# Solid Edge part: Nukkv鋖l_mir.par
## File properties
Author: Türk
Template: Iso Part.par
Last saved by: Türk
Revision: 7
Application: Solid Edge
Username: Türk
Accuracy: 0,990
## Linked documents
ll.par
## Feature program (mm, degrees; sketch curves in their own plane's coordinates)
part copy "CopiedPart_1"
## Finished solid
Body 1: solid body, 158 faces, 346 edges, 200 vertices.
  Faces by surface: cylinder 79, plane 79
  Edges by curve: line 188, circle 158
Bounding box of the edges (mm): 686.000 x 43.185 x 41.637, from (-4, -21.5925, -19.6372) to (682, 21.5925, 22).
Cylindrical faces by radius (mm): R1.75 x8, R5 x20, R9 x8, R10 x17, R12 x16, R22 x10
Planar faces by outward normal: +x 17, +y 3, +z 3, -x 18, -y 3, -z 3, oblique 32
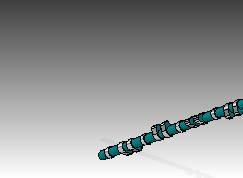
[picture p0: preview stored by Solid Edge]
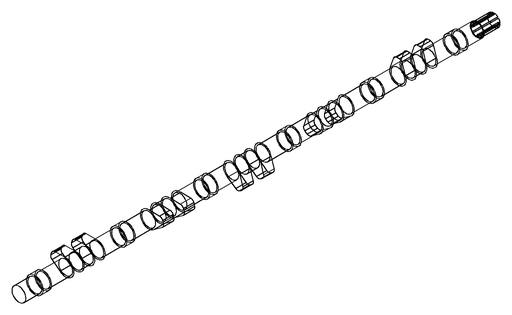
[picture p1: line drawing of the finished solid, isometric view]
